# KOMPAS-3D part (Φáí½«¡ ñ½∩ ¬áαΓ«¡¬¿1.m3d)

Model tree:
1. Эскиз:1
2. Операция выдавливания:1
     Толщина стенки 2 = 6; Расстояние 1 = 0.6
3. Эскиз:2
4. Операция выдавливания:2
     Толщина стенки 1 = 12; Толщина стенки 2 = 12; Расстояние 1 = 0.6; Расстояние 2 = 0.6
5. Эскиз:3
6. Операция выдавливания:3
     Толщина стенки 1 = 12; Толщина стенки 2 = 12; Расстояние 1 = 0.6; Расстояние 2 = 0.6
7. Эскиз:4
8. Операция выдавливания:4
     Толщина стенки 1 = 35; Толщина стенки 2 = 35; Расстояние 1 = 0.6; Расстояние 2 = 0.6
9. Эскиз:5
10. Вырезать элемент выдавливания:1
     Расстояние 1 = 10
11. Эскиз:6
12. Вырезать элемент выдавливания:2
     Расстояние 1 = 10
13. Эскиз:7
14. Вырезать элемент выдавливания:3
     Расстояние 1 = 10
